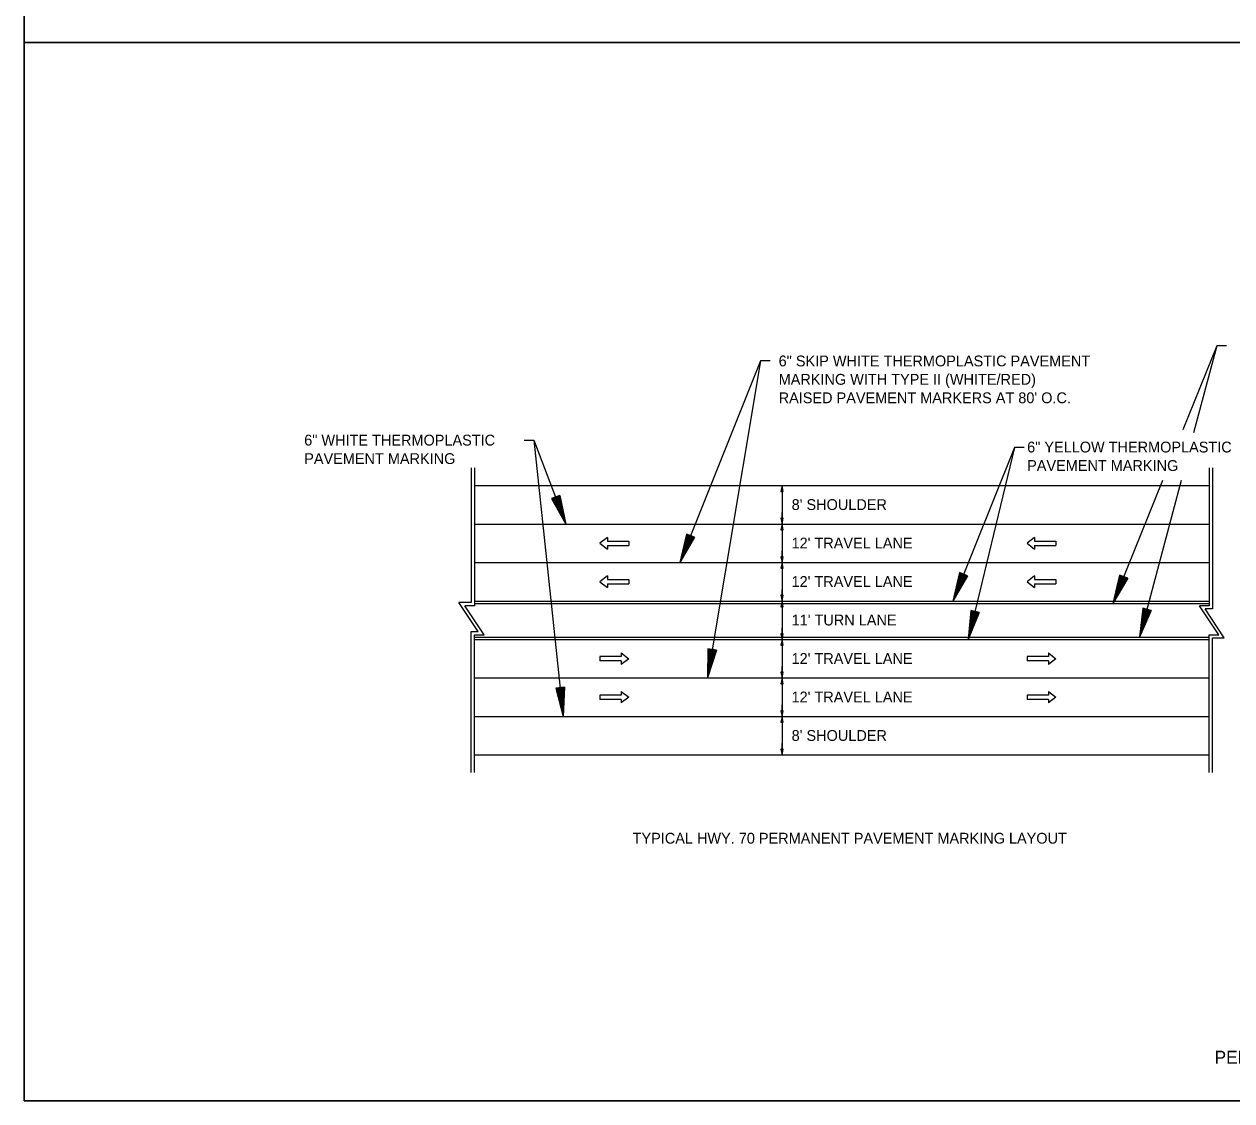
# Model space of a CAD drawing. Extents: x 2261938 to 2263136, y -3124572 to -3124216.
# Drawn here: x 2261937.6 to 2262063.2, y -3124572.5 to -3124460.6 of the extents above; entities that cross this region are included whole.
import ezdxf

# ---------------------------------------------------------------- set-up
doc = ezdxf.new("R2010")
doc.units = 0
for name, color, linetype in [('Default', 7, 'Continuous'), ('DSN_DRFT_Junk-No-Plot', 7, 'Continuous'), ('R_Border Notes', 7, 'Continuous'), ('R_Draft', 7, 'Continuous')]:
    doc.layers.add(name, color=color, linetype=linetype)

msp = doc.modelspace()

# ---------------------------------------------------------------- linework, layer by layer
at = {"layer": 'Default'}
for p, q in [((2262061.62, -3124493.99), (2262058.1, -3124502.73)), ((2262061.62, -3124493.99), (2262059.22, -3124503.03)), ((2262062.62, -3124493.99), (2262061.62, -3124493.99)), ((2262014.2, -3124495.57), (2262005.79, -3124516.52)), ((2262014.2, -3124495.57), (2262008.68, -3124528.52)), ((2262015.2, -3124495.57), (2262014.2, -3124495.57)), ((2261989.62, -3124503.8), (2261990.62, -3124503.8)), ((2261990.62, -3124503.8), (2261993.97, -3124512.52)), ((2261990.62, -3124503.8), (2261993.67, -3124532.52)), ((2262040.61, -3124504.56), (2262034.17, -3124520.52)), ((2262040.61, -3124504.56), (2262035.79, -3124524.52)), ((2262041.61, -3124504.56), (2262040.61, -3124504.56)), ((2261984.12, -3124506.68), (2261984.12, -3124520.69)), ((2261984.45, -3124506.68), (2261984.45, -3124521.02)), ((2262060.84, -3124506.68), (2262060.84, -3124521.02)), ((2262061.17, -3124506.68), (2262061.17, -3124521.35)), ((2262055.98, -3124507.98), (2262050.82, -3124520.77)), ((2262057.91, -3124507.98), (2262053.59, -3124524.27)), ((2261993.32, -3124509.56), (2261992.48, -3124509.88)), ((2261992.96, -3124509.69), (2261993.07, -3124510.16)), ((2261993.03, -3124509.67), (2261993.25, -3124510.63)), ((2261993.1, -3124509.64), (2261993.43, -3124511.1)), ((2261993.17, -3124509.61), (2261993.61, -3124511.57)), ((2261993.25, -3124509.59), (2261993.79, -3124512.05)), ((2261993.32, -3124509.56), (2261993.97, -3124512.52)), ((2261992.48, -3124509.88), (2261993.97, -3124512.52)), ((2261992.55, -3124509.85), (2261993.79, -3124512.05)), ((2261992.62, -3124509.83), (2261993.61, -3124511.57)), ((2261992.69, -3124509.8), (2261993.43, -3124511.1)), ((2261992.76, -3124509.77), (2261993.25, -3124510.63)), ((2261992.83, -3124509.74), (2261993.07, -3124510.16)), ((2261998.28, -3124513.92), (2261997.5, -3124514.52)), ((2261997.5, -3124514.52), (2261998.28, -3124515.12)), ((2261998.28, -3124513.92), (2261998.28, -3124514.3)), ((2261998.28, -3124514.3), (2262000.49, -3124514.3)), ((2262000.49, -3124514.3), (2262000.49, -3124514.75)), ((2262006.49, -3124513.57), (2262005.79, -3124516.52)), ((2262007.32, -3124513.9), (2262005.79, -3124516.52)), ((2262006.56, -3124513.6), (2262005.97, -3124516.06)), ((2262007.25, -3124513.88), (2262005.97, -3124516.06)), ((2262006.63, -3124513.63), (2262006.17, -3124515.58)), ((2262007.18, -3124513.85), (2262006.17, -3124515.58)), ((2262006.7, -3124513.65), (2262006.35, -3124515.11)), ((2262007.11, -3124513.82), (2262006.35, -3124515.11)), ((2262007.32, -3124513.9), (2262006.49, -3124513.57)), ((2262006.77, -3124513.68), (2262006.54, -3124514.64)), ((2262007.04, -3124513.79), (2262006.54, -3124514.64)), ((2262006.84, -3124513.71), (2262006.73, -3124514.18)), ((2262006.97, -3124513.76), (2262006.73, -3124514.18)), ((2262042.69, -3124513.92), (2262041.91, -3124514.52)), ((2262041.91, -3124514.52), (2262042.69, -3124515.12)), ((2262042.69, -3124513.92), (2262042.69, -3124514.3)), ((2262042.69, -3124514.3), (2262044.9, -3124514.3)), ((2262044.9, -3124514.3), (2262044.9, -3124514.75)), ((2261998.28, -3124514.75), (2262000.49, -3124514.75)), ((2261998.28, -3124514.75), (2261998.28, -3124515.12)), ((2262042.69, -3124514.75), (2262044.9, -3124514.75)), ((2262042.69, -3124514.75), (2262042.69, -3124515.12)), ((2261998.28, -3124517.92), (2261997.5, -3124518.52)), ((2261998.28, -3124517.92), (2261998.28, -3124518.3)), ((2261998.28, -3124518.3), (2262000.49, -3124518.3)), ((2262000.49, -3124518.3), (2262000.49, -3124518.75)), ((2262034.87, -3124517.57), (2262034.17, -3124520.52)), ((2262035.71, -3124517.91), (2262034.17, -3124520.52)), ((2262034.94, -3124517.6), (2262034.36, -3124520.06)), ((2262035.64, -3124517.88), (2262034.36, -3124520.06)), ((2262035.01, -3124517.63), (2262034.55, -3124519.58)), ((2262035.57, -3124517.85), (2262034.55, -3124519.58)), ((2262035.08, -3124517.65), (2262034.74, -3124519.11)), ((2262035.5, -3124517.82), (2262034.74, -3124519.11)), ((2262035.71, -3124517.91), (2262034.87, -3124517.57)), ((2262035.15, -3124517.68), (2262034.93, -3124518.64)), ((2262035.43, -3124517.79), (2262034.93, -3124518.64)), ((2262035.23, -3124517.71), (2262035.11, -3124518.18)), ((2262035.36, -3124517.76), (2262035.11, -3124518.18)), ((2262042.69, -3124517.92), (2262041.91, -3124518.52)), ((2262042.69, -3124517.92), (2262042.69, -3124518.3)), ((2262042.69, -3124518.3), (2262044.9, -3124518.3)), ((2262044.9, -3124518.3), (2262044.9, -3124518.75)), ((2262051.52, -3124517.82), (2262050.82, -3124520.77)), ((2262052.36, -3124518.16), (2262050.82, -3124520.77)), ((2262051.59, -3124517.85), (2262051.01, -3124520.31)), ((2262052.29, -3124518.13), (2262051.01, -3124520.31)), ((2262051.66, -3124517.88), (2262051.2, -3124519.83)), ((2262052.22, -3124518.1), (2262051.2, -3124519.83)), ((2262051.73, -3124517.9), (2262051.39, -3124519.36)), ((2262052.15, -3124518.07), (2262051.39, -3124519.36)), ((2262052.36, -3124518.16), (2262051.52, -3124517.82)), ((2262051.81, -3124517.93), (2262051.58, -3124518.89)), ((2262052.08, -3124518.04), (2262051.58, -3124518.89)), ((2262051.88, -3124517.96), (2262051.76, -3124518.43)), ((2262052.01, -3124518.01), (2262051.76, -3124518.43)), ((2261997.5, -3124518.52), (2261998.28, -3124519.12)), ((2261998.28, -3124518.75), (2262000.49, -3124518.75)), ((2261998.28, -3124518.75), (2261998.28, -3124519.12)), ((2262041.91, -3124518.52), (2262042.69, -3124519.12)), ((2262042.69, -3124518.75), (2262044.9, -3124518.75)), ((2262042.69, -3124518.75), (2262042.69, -3124519.12)), ((2261984.83, -3124523.69), (2261982.83, -3124520.69)), ((2261984.12, -3124520.69), (2261982.83, -3124520.69)), ((2261984.45, -3124521.02), (2261983.45, -3124521.02)), ((2261985.45, -3124524.02), (2261983.45, -3124521.02)), ((2262036.06, -3124521.5), (2262035.79, -3124524.52)), ((2262036.93, -3124521.71), (2262035.79, -3124524.52)), ((2262036.13, -3124521.52), (2262035.91, -3124524.03)), ((2262036.86, -3124521.69), (2262035.91, -3124524.03)), ((2262036.21, -3124521.53), (2262036.03, -3124523.53)), ((2262036.79, -3124521.67), (2262036.03, -3124523.53)), ((2262036.93, -3124521.71), (2262036.06, -3124521.5)), ((2262036.28, -3124521.55), (2262036.15, -3124523.05)), ((2262036.71, -3124521.66), (2262036.15, -3124523.05)), ((2262036.35, -3124521.57), (2262036.27, -3124522.55)), ((2262036.64, -3124521.64), (2262036.27, -3124522.55)), ((2262036.43, -3124521.59), (2262036.39, -3124522.06)), ((2262036.57, -3124521.62), (2262036.39, -3124522.06)), ((2262053.92, -3124521.26), (2262053.59, -3124524.27)), ((2262054.79, -3124521.49), (2262053.59, -3124524.27)), ((2262053.99, -3124521.27), (2262053.71, -3124523.79)), ((2262054.72, -3124521.47), (2262053.71, -3124523.79)), ((2262054.07, -3124521.29), (2262053.85, -3124523.29)), ((2262054.64, -3124521.45), (2262053.85, -3124523.29)), ((2262054.79, -3124521.49), (2262053.92, -3124521.26)), ((2262054.14, -3124521.31), (2262053.97, -3124522.8)), ((2262054.57, -3124521.43), (2262053.97, -3124522.8)), ((2262054.21, -3124521.33), (2262054.1, -3124522.31)), ((2262054.5, -3124521.41), (2262054.1, -3124522.31)), ((2262054.29, -3124521.35), (2262054.23, -3124521.83)), ((2262054.42, -3124521.39), (2262054.23, -3124521.83)), ((2262060.84, -3124521.02), (2262059.84, -3124521.02)), ((2262061.84, -3124524.02), (2262059.84, -3124521.02)), ((2262062.4, -3124524.35), (2262060.4, -3124521.35)), ((2262061.17, -3124521.35), (2262060.4, -3124521.35)), ((2261984.12, -3124523.69), (2261984.83, -3124523.69)), ((2261984.12, -3124538.36), (2261984.12, -3124523.69)), ((2261984.45, -3124538.36), (2261984.45, -3124524.02)), ((2261984.45, -3124524.02), (2261985.45, -3124524.02)), ((2262060.84, -3124538.36), (2262060.84, -3124524.02)), ((2262060.84, -3124524.02), (2262061.84, -3124524.02)), ((2262061.17, -3124538.36), (2262061.17, -3124524.35)), ((2262061.17, -3124524.35), (2262062.4, -3124524.35)), ((2261999.71, -3124525.92), (2261999.71, -3124526.3)), ((2261999.71, -3124525.92), (2262000.49, -3124526.52)), ((2262008.73, -3124525.49), (2262008.68, -3124528.52)), ((2262009.62, -3124525.64), (2262008.68, -3124528.52)), ((2262009.62, -3124525.64), (2262008.73, -3124525.49)), ((2262008.81, -3124525.5), (2262008.77, -3124528.03)), ((2262009.55, -3124525.62), (2262008.77, -3124528.03)), ((2262008.88, -3124525.51), (2262008.85, -3124527.52)), ((2262009.47, -3124525.61), (2262008.85, -3124527.52)), ((2262008.96, -3124525.52), (2262008.93, -3124527.02)), ((2262009.4, -3124525.6), (2262008.93, -3124527.02)), ((2262009.03, -3124525.54), (2262009.02, -3124526.52)), ((2262009.32, -3124525.59), (2262009.02, -3124526.52)), ((2262009.11, -3124525.55), (2262009.1, -3124526.03)), ((2262009.25, -3124525.57), (2262009.1, -3124526.03)), ((2262044.12, -3124525.92), (2262044.12, -3124526.3)), ((2262044.12, -3124525.92), (2262044.9, -3124526.52)), ((2261999.71, -3124526.3), (2261997.5, -3124526.3)), ((2261997.5, -3124526.3), (2261997.5, -3124526.75)), ((2261999.71, -3124526.75), (2261997.5, -3124526.75)), ((2262000.49, -3124526.52), (2261999.71, -3124527.12)), ((2261999.71, -3124526.75), (2261999.71, -3124527.12)), ((2262044.12, -3124526.3), (2262041.91, -3124526.3)), ((2262041.91, -3124526.3), (2262041.91, -3124526.75)), ((2262044.12, -3124526.75), (2262041.91, -3124526.75)), ((2262044.9, -3124526.52), (2262044.12, -3124527.12)), ((2262044.12, -3124526.75), (2262044.12, -3124527.12)), ((2261993.8, -3124529.49), (2261992.9, -3124529.58)), ((2261992.9, -3124529.58), (2261993.67, -3124532.52)), ((2261992.98, -3124529.58), (2261993.61, -3124532.02)), ((2261993.05, -3124529.57), (2261993.56, -3124531.51)), ((2261993.13, -3124529.56), (2261993.51, -3124531.01)), ((2261993.2, -3124529.55), (2261993.45, -3124530.51)), ((2261993.28, -3124529.54), (2261993.4, -3124530.01)), ((2261993.42, -3124529.53), (2261993.4, -3124530.01)), ((2261993.5, -3124529.52), (2261993.45, -3124530.51)), ((2261993.57, -3124529.51), (2261993.51, -3124531.01)), ((2261993.65, -3124529.51), (2261993.56, -3124531.51)), ((2261993.72, -3124529.5), (2261993.61, -3124532.02)), ((2261993.8, -3124529.49), (2261993.67, -3124532.52)), ((2261999.71, -3124530.3), (2261997.5, -3124530.3)), ((2261997.5, -3124530.3), (2261997.5, -3124530.75)), ((2261999.71, -3124530.75), (2261997.5, -3124530.75)), ((2261999.71, -3124529.92), (2261999.71, -3124530.3)), ((2261999.71, -3124529.92), (2262000.49, -3124530.52)), ((2262000.49, -3124530.52), (2261999.71, -3124531.12)), ((2261999.71, -3124530.75), (2261999.71, -3124531.12)), ((2262044.12, -3124530.3), (2262041.91, -3124530.3)), ((2262041.91, -3124530.3), (2262041.91, -3124530.75)), ((2262044.12, -3124530.75), (2262041.91, -3124530.75)), ((2262044.12, -3124529.92), (2262044.12, -3124530.3)), ((2262044.12, -3124529.92), (2262044.9, -3124530.52)), ((2262044.9, -3124530.52), (2262044.12, -3124531.12)), ((2262044.12, -3124530.75), (2262044.12, -3124531.12))]:
    msp.add_line(p, q, dxfattribs=at)
at = {"layer": 'DSN_DRFT_Junk-No-Plot'}
msp.add_line((2262016.43, -3124508.52), (2262016.43, -3124536.52), dxfattribs=at)
for points in [[(2261937.65, -3124352.47), (2262107.65, -3124352.47), (2262107.65, -3124462.47), (2261937.65, -3124462.47)], [(2261937.65, -3124352.47), (2261937.65, -3124462.47), (2262107.65, -3124462.47), (2262107.65, -3124352.47)], [(2261937.65, -3124462.47), (2262107.65, -3124462.47), (2262107.65, -3124572.47), (2261937.65, -3124572.47)], [(2261937.65, -3124462.47), (2261937.65, -3124572.47), (2262107.65, -3124572.47), (2262107.65, -3124462.47)]]:
    msp.add_lwpolyline(points, close=True, dxfattribs=at)
for points in [[(2262016.43, -3124508.52), (2262016.31, -3124509.12), (2262016.55, -3124509.12), (2262016.43, -3124508.52), (2262016.43, -3124509.72)], [(2262016.43, -3124512.52), (2262016.55, -3124511.92), (2262016.31, -3124511.92), (2262016.43, -3124512.52), (2262016.43, -3124511.32)], [(2262016.43, -3124512.52), (2262016.31, -3124513.12), (2262016.55, -3124513.12), (2262016.43, -3124512.52), (2262016.43, -3124513.72)], [(2262016.43, -3124516.52), (2262016.55, -3124515.92), (2262016.31, -3124515.92), (2262016.43, -3124516.52), (2262016.43, -3124515.32)], [(2262016.43, -3124516.52), (2262016.31, -3124517.12), (2262016.55, -3124517.12), (2262016.43, -3124516.52), (2262016.43, -3124517.72)], [(2262016.43, -3124520.52), (2262016.55, -3124519.92), (2262016.31, -3124519.92), (2262016.43, -3124520.52), (2262016.43, -3124519.32)], [(2262016.43, -3124520.52), (2262016.31, -3124521.12), (2262016.55, -3124521.12), (2262016.43, -3124520.52), (2262016.43, -3124521.72)], [(2262016.43, -3124524.52), (2262016.55, -3124523.92), (2262016.31, -3124523.92), (2262016.43, -3124524.52), (2262016.43, -3124523.32)], [(2262016.43, -3124524.52), (2262016.31, -3124525.12), (2262016.55, -3124525.12), (2262016.43, -3124524.52), (2262016.43, -3124525.72)], [(2262016.43, -3124528.52), (2262016.55, -3124527.92), (2262016.31, -3124527.92), (2262016.43, -3124528.52), (2262016.43, -3124527.32)], [(2262016.43, -3124528.52), (2262016.31, -3124529.12), (2262016.55, -3124529.12), (2262016.43, -3124528.52), (2262016.43, -3124529.72)], [(2262016.43, -3124532.52), (2262016.55, -3124531.92), (2262016.31, -3124531.92), (2262016.43, -3124532.52), (2262016.43, -3124531.32)], [(2262016.43, -3124532.52), (2262016.31, -3124533.12), (2262016.55, -3124533.12), (2262016.43, -3124532.52), (2262016.43, -3124533.72)], [(2262016.43, -3124536.52), (2262016.55, -3124535.92), (2262016.31, -3124535.92), (2262016.43, -3124536.52), (2262016.43, -3124535.32)]]:
    msp.add_lwpolyline(points, dxfattribs=at)
at = {"layer": 'R_Draft'}
for p, q in [((2261984.45, -3124508.52), (2262060.84, -3124508.52)), ((2261984.45, -3124512.52), (2262060.84, -3124512.52)), ((2261984.45, -3124516.52), (2262060.84, -3124516.52)), ((2261984.45, -3124520.52), (2262060.84, -3124520.52)), ((2261984.45, -3124520.77), (2262060.84, -3124520.77)), ((2261984.45, -3124524.27), (2262060.84, -3124524.27)), ((2261984.45, -3124524.52), (2262060.84, -3124524.52)), ((2261984.45, -3124528.52), (2262060.84, -3124528.52)), ((2261984.45, -3124532.52), (2262060.84, -3124532.52)), ((2261984.45, -3124536.52), (2262060.84, -3124536.52))]:
    msp.add_line(p, q, dxfattribs=at)

# ---------------------------------------------------------------- texts
at = {"layer": 'Default'}
for s, p in [('6" SKIP WHITE THERMOPLASTIC PAVEMENT', (2262016.08, -3124496.13)), ('MARKING WITH TYPE II (WHITE/RED)', (2262016.08, -3124498.04)), ("RAISED PAVEMENT MARKERS AT 80' O.C.", (2262016.08, -3124499.96)), ('6" WHITE THERMOPLASTIC', (2261966.76, -3124504.36)), ('6" YELLOW THERMOPLASTIC', (2262041.91, -3124505.08)), ('PAVEMENT MARKING', (2261966.76, -3124506.28)), ('PAVEMENT MARKING', (2262041.91, -3124507))]:
    msp.add_text(s, height=1.125, dxfattribs=at).set_placement(p)
at = {"layer": 'R_Border Notes'}
msp.add_text('PERMANENT PAVEMENT MARKING DETAILS', height=1.35, dxfattribs=at).set_placement((2262061.39, -3124568.62))
at = {"layer": 'R_Draft'}
for s, p in [("8' SHOULDER", (2262017.43, -3124511.06)), ("12' TRAVEL LANE", (2262017.42, -3124515.06)), ("12' TRAVEL LANE", (2262017.42, -3124519.06)), ("11' TURN LANE", (2262017.43, -3124523.06)), ("12' TRAVEL LANE", (2262017.42, -3124527.06)), ("12' TRAVEL LANE", (2262017.42, -3124531.06)), ("8' SHOULDER", (2262017.43, -3124535.06)), ('TYPICAL HWY. 70 PERMANENT PAVEMENT MARKING LAYOUT', (2262000.9, -3124545.74))]:
    msp.add_text(s, height=1.125, dxfattribs=at).set_placement(p)

doc.saveas('drawing.dxf')
